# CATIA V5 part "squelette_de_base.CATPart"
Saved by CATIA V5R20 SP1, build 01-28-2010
Part number: squelette_de_base.1
Publications: "Hardpoint1", "Hardpoint2", "Hardpoint4", "RefPlane", "excentrique", "decalage", "Point.5", "Point.6", "Point.8", "Point.9", "Point.10", "excentration", "Point.11", "Droite.3", "Point.13", "Droite.2", "Droite.4", "Point.14", "Point.15", "Hauteur_bati"
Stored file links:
  C:\Users\Fox\Desktop\IAO Projet\A RENDRE\Sauvegarde IFMA\squelette_de_base.CATPart

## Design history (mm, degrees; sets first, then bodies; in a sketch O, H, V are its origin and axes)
Parameters
  excentrique = 100 mm
  decalage = 10 mm
  excentration = 25 mm
  Hauteur_bati = 500 mm
Set1
  Point1: (0, 10 {= decalage}, 0)
  Point2: (0, 60 {= decalage+excentrique*cos(PI/3)}, 86.6025 {= excentrique*sin(PI/3)})
  Point3: (0, 500 {= Hauteur_bati}, 0)
  Plane1: type Offset, RefPlane yz-plane, Offset 0
  Point4: (0, 60 {= decalage+excentrique*cos(-PI/3)}, -86.6025 {= excentrique*sin(-PI/3)})
  Point5: (0, -90 {= decalage-excentrique}, 0)
  Point6: (-5, 20.134, 0), relative to Point5
  Point7: (5, 500 {= Hauteur_bati}, 0)
  Point8: (-5, 500 {= Hauteur_bati}, 0)
  Line1: type PtPt, FirstPoint Point2, SecondPoint Point3
  Point9: type OnCurve, Support Line1, Length 25 {= excentration}
  Line2: type PtPt, FirstPoint Point4, SecondPoint Point3
  Point10: type OnCurve, Support Line2, Length 25 {= excentration}
  Line3: type PtPt, FirstPoint Point5, SecondPoint Point3
  Point11: type OnCurve, Support Line3, RefPoint Point5, Length 25 {= excentration}
  Point12: (5, 500 {= Hauteur_bati}, 0)
Body1 (main body)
